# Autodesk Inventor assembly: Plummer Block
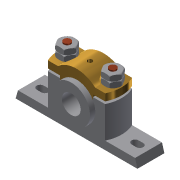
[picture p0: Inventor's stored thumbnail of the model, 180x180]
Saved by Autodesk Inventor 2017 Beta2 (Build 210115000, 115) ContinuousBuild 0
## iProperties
Created: 2011-07
Part Number: Plummer Block
Document SubType Name: Assembly
Designer: CadCim
Author: CadCim
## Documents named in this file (7)
- D:\KAVITA\Autodesk Inventor_ 2016 Project_Kavita\Inventor_Part Files\Inventor_2016_Part\c11_Inv_2016\c11_inv_2016_prt\figure-11-23 through 11-26\Plummer Block.iam
- D:\KAVITA\Autodesk Inventor_ 2016 Project_Kavita\Inventor_Part Files\Inventor_2016_Part\c11_Inv_2016\c11_inv_2016_prt\figure-11-23 through 11-26\Casting.ipt
- D:\KAVITA\Autodesk Inventor_ 2016 Project_Kavita\Inventor_Part Files\Inventor_2016_Part\c11_Inv_2016\c11_inv_2016_prt\figure-11-23 through 11-26\Brasses.ipt
- D:\KAVITA\Autodesk Inventor_ 2016 Project_Kavita\Inventor_Part Files\Inventor_2016_Part\c11_Inv_2016\c11_inv_2016_prt\figure-11-23 through 11-26\Cap.ipt
- D:\KAVITA\Autodesk Inventor_ 2016 Project_Kavita\Inventor_Part Files\Inventor_2016_Part\c11_Inv_2016\c11_inv_2016_prt\figure-11-23 through 11-26\Bolt.ipt
- D:\KAVITA\Autodesk Inventor_ 2016 Project_Kavita\Inventor_Part Files\Inventor_2016_Part\c11_Inv_2016\c11_inv_2016_prt\figure-11-23 through 11-26\Nut.ipt
- D:\KAVITA\Autodesk Inventor_ 2016 Project_Kavita\Inventor_Part Files\Inventor_2016_Part\c11_Inv_2016\c11_inv_2016_prt\figure-11-23 through 11-26\Lock Nut.ipt
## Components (9 placed, 6 different names)
1. Casting:1 — Mate:1, Mate:2, Insert:1, Insert:2, Angle:1, Angle:2
2. Brasses:1 — Mate:1, Mate:2, Mate:3, Mate:4
3. Cap:1 — Mate:3, Mate:4, Insert:3, Insert:4
4. Bolt:1 — Insert:1, Angle:1
5. Bolt:2 — Insert:2, Angle:2
6. Nut:1 — Insert:3, Insert:6
7. Nut:2 — Insert:4, Insert:5
8. Lock Nut:1 — Insert:6
9. Lock Nut:2 — Insert:5
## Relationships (12: Insert 6, Mate 4, Angle 2)
- Mate:1: Casting:1 ↔ Brasses:1
- Mate:2: Casting:1 ↔ Brasses:1
- Mate:3: Brasses:1 ↔ Cap:1
- Mate:4: Brasses:1 ↔ Cap:1
- Insert:1: Casting:1 ↔ Bolt:1
- Insert:2: Casting:1 ↔ Bolt:2
- Angle:1: Casting:1 ↔ Bolt:1
- Angle:2: Casting:1 ↔ Bolt:2
- Insert:3: Cap:1 ↔ Nut:1
- Insert:4: Cap:1 ↔ Nut:2
- Insert:5: Nut:2 ↔ Lock Nut:2
- Insert:6: Nut:1 ↔ Lock Nut:1
